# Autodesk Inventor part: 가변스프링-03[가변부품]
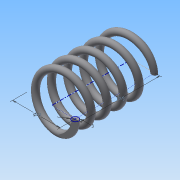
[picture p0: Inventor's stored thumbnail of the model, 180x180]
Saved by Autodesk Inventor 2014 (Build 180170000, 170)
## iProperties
Created: 2015-09
Part Number: 가변스프링-03[가변부품]
Material: 강철, 탄소
Document SubType Name: Modeling
Designer: study
Density: 7.87 g/cm^3
Appearance: 반연마
Mass: 18.8856 g
Surface Area: 32.5491 cm^2
Volume: 2.3997 cm^3
Author: study
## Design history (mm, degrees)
sketch "스케치1"
  geometry: L1 (0, 0)-(11, 0); L2 (11, 0)-(11, 36.411); L3 (11, 36.411)-(0, 36.411); L4 (0, 36.411)-(0, 0); C1 r 1.5 at (11, 0)
  constraints: 8 end point, 2 parallel, 1 centre point, 1 coincident, 1 horizontal, 1 perpendicular
  dimensions: "d0" = 36.4112 distance of L1.end L2.end (derived); "d1" = 22 diameter of L2 L4; "d2" = 3 diameter of C1
feature "코일1" sketch "스케치1" pitch "d3" = 10; turns "d5" = 5; dims "d4" = 36.4112 (= d0), "d6" = 0, angle "d7" = 90 deg, angle "d8" = 90 deg, "d9" = 0, "d10" = 0
node "작업 평면1"
sketch "스케치2"
  geometry: L1 (-12.5, 0)-(-9.5, 0) reference; 1 further point
  constraints: 1 horizontal alignment
extrude "돌출1" cut sketch "스케치2" stored distance "d12" = 10; taper "d13" = 0 deg
node "작업 평면2"
sketch "스케치3"
  geometry: L1 (-9.5, 0)-(-12.5, 0) reference; 1 further point
  constraints: 1 horizontal alignment
extrude "돌출2" cut sketch "스케치3" stored distance "d15" = 10; taper "d16" = 0 deg
node "솔리드1"
node "절단 모서리 투영1"
node "절단 모서리 투영2"
other parameters: "d11" = 0, "d14" = 36.4112 (= d0)
